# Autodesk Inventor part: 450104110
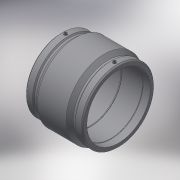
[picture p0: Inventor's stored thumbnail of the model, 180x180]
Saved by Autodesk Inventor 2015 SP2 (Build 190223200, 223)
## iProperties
Created: 2017-06
Part Number: 450104110
Material: Generic
Description: PLASSON COUPLER 110 PN25
Document SubType Name: Modeling
Designer: KIM
Mass: 8622.19 g
Surface Area: 6772.47 cm^2
Volume: 8622.19 cm^3
Density: 1 g/cm^3
Appearance: Default
Author: KIM
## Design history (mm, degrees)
derived "450104.ipt"
feature "Solid1::450104.ipt"
tag "TaggingFeature1"
body "Solid1"
other parameters: "d0" = 163, "d4" = 40.75, "d5" = 126, "d6" = 88, "d8" = 168 deg, "d10" = 32, "d11" = 10.66667, "d13" = 163, "d14" = 17.6296, "d17" = 108.9, "d19" = 3.52592, "d20" = 168 deg, "d22" = 131.6, "d24" = 127.652, "d25" = 135 deg, "d26" = 73.35, "d27" = 135 deg, "d29" = 79, "d30" = 15, "d31" = 57.05, "d34" = 5 deg, "d35" = 15, "d39" = 5 deg, "d41" = 4, "d42" = 14, "d43" = 0, "d45" = 4, "d46" = 14, "d47" = 0, "d48" = 3, "d49" = 0, "d50" = 3, "d51" = 0, "d52" = 23.2, "d53" = 5.8, "L_" = 163, "A_" = 79, "d_2" = 12
